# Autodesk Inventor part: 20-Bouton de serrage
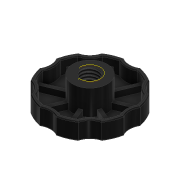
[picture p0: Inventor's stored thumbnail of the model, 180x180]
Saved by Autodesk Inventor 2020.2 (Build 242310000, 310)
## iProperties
Created: 2022-03
Part Number: 20-Bouton de serrage
Material: Nylon 6/6
Document SubType Name: Modeling
Designer: %USERNAME%
Density: 1.13 g/cm^3
Appearance: Lisse - Noir
Author: %USERNAME%
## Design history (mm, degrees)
sketch "Esquisse2"
  geometry: L1 (0, 0)-(21, 0); L2 (21, 0)-(21, -1.7); L3 (21, -1.7)-(0, -1.7); L4 (0, -1.7)-(0, 0); L5 (0, 0)-(8.5, 0); L6 (8.5, 0)-(8.5, 12.3); L7 (8.5, 12.3)-(0, 12.3); L8 (0, 12.3)-(0, 0); L9 (21, 0)-(0, 0); L10 (0, 0)-(0, 6.8); L11 (0, 6.8)-(21, 6.8); L12 (21, 6.8)-(21, 0); L13 (0, 12.3)-(4, 12.3); L14 (4, 12.3)-(4, 0); L15 (4, 0)-(0, 0); L16 (0, 0)-(0, 12.3); 4 further points
  constraints: 32 end point, 8 parallel, 4 horizontal, 4 perpendicular, 1 collinear, 1 point on line
  dimensions: "d0" = 17 diameter of L6 L8; "d1" = 8 diameter of L14 L8; "d2" = 14 distance between parallel lines of L3 L7; "d3" = 8.5 distance between parallel lines of L3 L11; "d4" = 6.8 distance of L11.end L1.end; "d5" = 42 diameter of L12 L8
revolve "Révolution1" stored, may be unused: angle "d6" = 90 deg
revolve "Révolution2" stored, may be unused: angle "d7" = 90 deg
sketch "Esquisse3"
  geometry: C1 r 8 at (27.5, 0); 1 further point
  constraints: 1 centre point, 1 horizontal alignment
  dimensions: "d8" = 16 diameter of C1; "d9" = 27.5 distance of C1.centre point (0, 0)
extrude "Extrusion1" cut sketch "Esquisse3" distance "d10" = 10; taper "d11" = 0 deg
pattern_circular "Réseau circulaire1" dims angle "d13" = 360 deg
feature "Coque1" dims "d15" = 1.7
fillet "Congé1" dims "d35" = 0.5
feature "Combiner1"
  node "Solide2"
sketch "Esquisse4"
  geometry: C1 r 8.5 at (0, 0) reference; 1 further point
  constraints: 1 coincident
hole "Perçage1" sketch "Esquisse4" at (0, 0) diameter "d16" = 8.376; stored, may be unused: countersink angle "d20" = 90 deg, drill point angle "d22" = 0 deg; dims "d17" = 10, "d18" = 4, "d19" = 2, "d21" = 12.3
node "Plan de construction1"
sketch "Esquisse5"
  geometry: L1 (3, -7.924)-(3, -19.623); L2 (0, -11.184)-(0, -3.214) reference; 1 further point
  constraints: 2 end point, 1 vertical
  dimensions: "d24" = 3 distance between parallel lines of L2 L1
feature "Nervure1" sketch "Esquisse5" dims "d26" = 1, "d27" = 1.7, "d28" = 0, "d29" = 0, "d30" = 1, "d31" = 1
pattern_circular "Réseau circulaire2" dims angle "d33" = 360 deg
sketch "Esquisse6"
  geometry: A1 r 5 centre (0, 0) between (-0.441, -4.98) and (-5, 0); 1 further point
  constraints: 2 point on circle, 1 centre point, 1 coincident
  dimensions: "d36" = 5 radius of A1
feature "SrfExtrusion1" sketch "Esquisse6" dims "d37" = 0.5, "d38" = 10, "d39" = 0, "d40" = 0
node "Solide1"
body "Srf1"
other parameters: "d23" = 22.5 deg
